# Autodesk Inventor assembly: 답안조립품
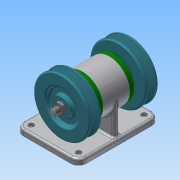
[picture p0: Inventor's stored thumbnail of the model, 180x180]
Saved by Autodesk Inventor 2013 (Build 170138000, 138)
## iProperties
Created: 2019-09
Part Number: 답안조립품
Document SubType Name: Assembly
Designer: Administrator
Author: Administrator
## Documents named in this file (10)
- C:\Users\Administrator\Desktop\490904V1052\답안조립품.iam
- C:\Users\Administrator\Desktop\490904V1052\본체.ipt
- C:\Users\Administrator\Desktop\490904V1052\V-벨트풀리.ipt
- C:\Users\Administrator\Desktop\490904V1052\너트 M10x1.ipt
- C:\Users\Administrator\Desktop\490904V1052\베어링 6004.ipt
- C:\Users\Administrator\Desktop\490904V1052\볼트 M4.ipt
- C:\Users\Administrator\Desktop\490904V1052\오일 실 17 30 5.ipt
- C:\Users\Administrator\Desktop\490904V1052\축.ipt
- C:\Users\Administrator\Desktop\490904V1052\커버.ipt
- C:\Users\Administrator\Desktop\490904V1052\키 5 x 5 x 12.ipt
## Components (2 placed, 1 different names)
1. V-벨트풀리:1 — 각도:1
2. V-벨트풀리:2
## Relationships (1: Angle 1)
- 각도:1 [Angle]: V-벨트풀리:1
